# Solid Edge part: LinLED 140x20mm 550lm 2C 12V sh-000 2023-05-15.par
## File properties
Author: jaroslaw.przewlocki
Template: iso metric part.par
Last saved by: jaroslaw.przewlocki
Revision: 2
Application: Solid Edge
Gęstość: 0,000 kg/m^3
Dokładność: 0,990
Username: jaroslaw.przewlocki
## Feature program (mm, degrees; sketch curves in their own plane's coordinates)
body "unnamed Body 1"
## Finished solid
Body 1: solid body, 774 faces, 1990 edges, 1268 vertices.
  Faces by surface: plane 472, cylinder 146, torus 64, cone 50, spline 26, sphere 16
  Edges by curve: line 1350, curve on surface 356, circle 182, ellipse 66, spline 36
Bounding box of the edges (mm; curved faces can reach further): 139.600 x 20.000 x 4.450, from (-69.8, -10, 0) to (69.8, 10, 4.45).
Cylindrical faces by radius (mm): R0.2 x46, R0.2169 x6, R0.25 x20, R0.3373 x6, R0.4 x8, R0.4006 x2, R0.4008 x2, R0.525 x2, R0.6 x20, R1 x12, R1.1 x4, R1.1989 x2, R1.199 x2, R1.2 x10, R2.15 x4
Conical faces (half-angle, radius in mm at the cone's reference point): 0.398 deg R1.1964 x2, 0.4493 deg R1.1964 x2, 0.4746 deg R1.1948 x2, 0.4758 deg R1.1948 x2, 0.5 deg R0.5056 x4, 0.5 deg R1.0082 x4, 1 deg R0.5511 x2, 10 deg R0.2132 x4, 10 deg R0.4132 x4, 16.0099 deg R1.1053 x2, 16.1249 deg R1.1279 x2, 18.8604 deg R1.0669 x4, 19.5041 deg R0.5138 x2, 19.8244 deg R0.5099 x2, 27.363 deg R0.6214 x2, 40.6434 deg R0.5161 x2, 43.3309 deg R0.4892 x2, 45 deg R0.575 x2, 45 deg R0.625 x4
Toroidal faces (ring radius, tube radius in mm): R0.0958 r0.3997 x4, R0.1076 r0.4 x2, R0.1101 r0.4001 x2, R0.1217 r0.4 x2, R0.1234 r0.4 x2, R0.1626 r0.228 x2, R0.1634 r0.2287 x2, R0.3287 r0.2001 x2, R0.3684 r0.2151 x2, R0.3703 r0.4 x2, R0.3818 r0.2 x4, R0.4166 r0.3983 x2, R0.5981 r0.197 x2, R0.5982 r0.197 x2, R0.6009 r0.3968 x2, R0.6009 r0.3969 x2, R0.6227 r0.2 x2, R0.6235 r0.2 x2, R0.8 r0.2 x4, R0.8522 r0.3 x2, R0.9002 r0.2 x2, R0.9018 r0.2 x2, R0.9197 r0.223 x2, R0.9365 r0.2 x2, R0.9663 r0.2263 x2, R0.9665 r0.2263 x2, R1.429 r1.2 x2, R1.8741 r0.2175 x2, R1.9007 r0.2 x2
Spherical faces by radius (mm): R0.2 x12, R0.6 x4
Planar faces by outward normal: +x 52, +y 55, +z 73, -x 52, -y 55, -z 9, oblique 176
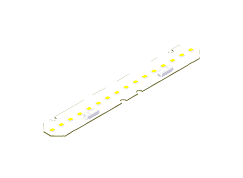
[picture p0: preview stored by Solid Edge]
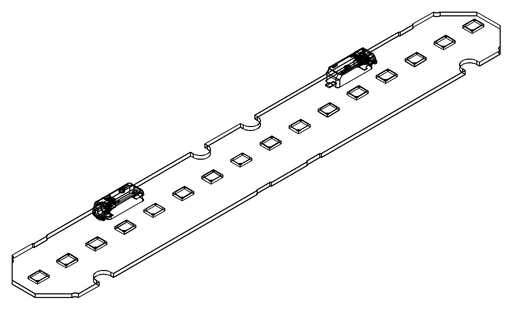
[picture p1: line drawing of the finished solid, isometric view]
